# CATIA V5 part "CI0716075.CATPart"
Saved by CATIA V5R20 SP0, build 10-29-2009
Part number: CI0716075_ASM
Bounding box of the stored display mesh (mm): x -15 to 15, y -11.845 to 99, z -15.201 to 17.744
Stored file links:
  C:\Users\Raffaele\Desktop\3D X SITO CF\BOLEX\19-INCLINED ASSEMBLY REF_CI\CI0716075.CATPart
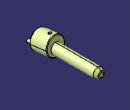
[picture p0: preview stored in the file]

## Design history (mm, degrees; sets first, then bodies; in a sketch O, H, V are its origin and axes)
Set1
  DatumSurface1 to DatumSurface16 "MANIFOLD_SOLID_BREP #381"
  DatumSurface17 to DatumSurface39 "MANIFOLD_SOLID_BREP #1106"
Body1 (main body)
